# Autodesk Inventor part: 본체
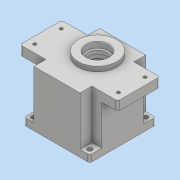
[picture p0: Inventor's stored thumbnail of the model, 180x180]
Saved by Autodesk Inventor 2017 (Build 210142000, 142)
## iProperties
Part Number: 본체
Material: 일반
Document SubType Name: Modeling
Designer: user
Density: 1 g/cm^3
Appearance: 기본값
Author: user
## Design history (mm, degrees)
sketch "스케치3"
  geometry: L1 (33, 47)-(-33, 47); L2 (-33, 47)-(-33, -47); L3 (-33, -47)-(33, -47); L4 (33, -47)-(33, 47); L5 (33, 47)-(-33, -47); L6 (-33, 47)-(33, -47); L7 (70, 30)-(-70, 30); L8 (-70, 30)-(-70, -30); L9 (-70, -30)-(70, -30); L10 (70, -30)-(70, 30); L11 (70, 30)-(-70, -30); L12 (-70, 30)-(70, -30); 1 further point
  constraints: 24 end point, 4 midpoint, 4 parallel, 2 horizontal, 2 perpendicular
  dimensions: "d12" = 66 distance of L3.end L2.end; "d13" = 94 distance of L2.end L1.end; "d14" = 140 distance of L9.end L8.end; "d15" = 60 distance of L8.end L7.end
extrude "돌출2" new body sketch "스케치3" distance "d16" = 13; taper "d17" = 0 deg
node "작업 평면1"
sketch "스케치4"
  geometry: L1 (-47, 47)-(47, 47); L2 (47, 47)-(47, -47); L3 (47, -47)-(-47, -47); L4 (-47, -47)-(-47, 47); L5 (-47, 47)-(47, -47); L6 (47, 47)-(-47, -47); 1 further point
  constraints: 12 end point, 2 midpoint, 2 parallel, 1 horizontal, 1 perpendicular
  dimensions: "d19" = 94 distance of L2.end L3.end; "d20" = 94 distance of L1.end L2.end
extrude "돌출3" join sketch "스케치4" distance "d21" = 10; taper "d22" = 0 deg
sketch "스케치5"
  geometry: L1 (-33, -30)-(-33, -47) reference; L2 (33, 47)-(-33, 47); L3 (-33, 47)-(-33, -47); L4 (-33, -47)-(33, -47); L5 (33, -47)-(33, 47); L6 (33, 47)-(-33, -47); L7 (-33, 47)-(33, -47); L8 (-47, 47)-(-47, -47) reference; L9 (47, 30)-(-47, 30); L10 (-47, 30)-(-47, -30); L11 (-47, -30)-(47, -30); L12 (47, -30)-(47, 30); L13 (47, 30)-(-47, -30); L14 (-47, 30)-(47, -30); L15 (70, 30)-(33, 30) reference; 1 further point
  constraints: 24 end point, 4 midpoint, 4 parallel, 2 horizontal, 2 perpendicular, 2 point on line
extrude "돌출4" join sketch "스케치5" distance "d23" = 70; taper "d24" = 0 deg
sketch "스케치6"
  geometry: C1 r 27.5 at (0, 11); 1 further point
  constraints: 1 centre point, 1 vertical alignment
  dimensions: "d25" = 55 diameter of C1; "d26" = 11 distance of point (0, 0) C1.centre
extrude "돌출5" join sketch "스케치6" distance "d27" = 7; taper "d28" = 0 deg
hole "구멍1" diameter "d31" = 32; stored, may be unused: countersink angle "d35" = 90 deg, drill point angle "d37" = 0 deg; dims "d29" = 10, "d30" = 10, "d32" = 6, "d33" = 4, "d34" = 2, "d36" = 8.3
sketch "스케치7"
  geometry: C1 r 12.5 at (0, 0); C2 r 16 at (0, 0) reference; 1 further point
  constraints: 1 centre point, 1 concentric
  dimensions: "d38" = 25 diameter of C1
extrude "돌출6" cut sketch "스케치7" distance "d39" = 4.7; taper "d40" = 0 deg
sketch "스케치8"
  geometry: C1 r 17.5 at (0, 0); C2 r 16 at (0, 0) reference; 1 further point
  constraints: 1 centre point, 1 concentric
  dimensions: "d41" = 35 diameter of C1
extrude "돌출7" cut sketch "스케치8" distance "d42" = 10; taper "d43" = 0 deg
sketch "스케치9"
  geometry: C1 r 43 at (0, 0); 1 further point
  constraints: 2 coincident, 1 centre point
  dimensions: "d44" = 86 diameter of C1
extrude "돌출8" cut sketch "스케치9" distance "d45" = 9; taper "d46" = 0 deg
sketch "스케치10"
  geometry: C1 r 40 at (0, 0); C2 r 43 at (0, 0) reference; 1 further point
  constraints: 1 centre point, 1 concentric
  dimensions: "d47" = 80 diameter of C1
extrude "돌출9" cut sketch "스케치10" distance "d48" = 62; taper "d49" = 0 deg
sketch "스케치11"
  geometry: 2 further points
  dimensions: "d50" = 19 vertical distance of point (0, 0) point (-60, 19); "d51" = 60 horizontal distance of point (0, 0) point (-60, 19)
hole "구멍2" sketch "스케치11" at (-60, 19) diameter "d52" = 4.5; stored, may be unused: countersink angle "d56" = 90 deg, drill point angle "d58" = 0 deg; dims "d53" = 6, "d54" = 10, "d55" = 5, "d57" = 13
sketch "스케치12"
  geometry: 2 further points
  dimensions: "d65" = 40 horizontal distance of point (0, 0) point (40, 40); "d66" = 40 horizontal distance of point (0, 0) point (40, 40)
hole "구멍3" sketch "스케치12" at (40, 40) diameter "d67" = 7; stored, may be unused: countersink angle "d71" = 90 deg, drill point angle "d73" = 0 deg; dims "d68" = 6, "d69" = 10, "d70" = 5, "d72" = 30
sketch "스케치13"
  geometry: C1 r 21 at (0, 11); C2 r 15 at (0, -20); 1 further point
  constraints: 2 centre point, 2 vertical alignment
  dimensions: "d80" = 42 diameter of C1; "d81" = 30 diameter of C2; "d82" = 11 distance of point (0, 0) C1.centre; "d83" = 20 distance of C2.centre point (0, 0)
extrude "돌출10" join sketch "스케치13" distance "d84" = 7; taper "d85" = 0 deg
hole "구멍4" diameter "d88" = 35; stored, may be unused: countersink angle "d92" = 90 deg, drill point angle "d94" = 0 deg; dims "d86" = 10, "d87" = 10, "d89" = 6, "d90" = 10, "d91" = 5, "d93" = 10
sketch "스케치14"
  geometry: C1 r 11 at (0, -20); A1 r 15 centre (0, -20) between (-8.978, -7.984) and (8.978, -7.984) reference; 1 further point
  constraints: 1 centre point, 1 concentric
  dimensions: "d95" = 22 diameter of C1
extrude "돌출11" cut sketch "스케치14" distance "d96" = 7; taper "d97" = 0 deg
sketch "스케치15"
  geometry: C1 r 9.5 at (0, 0); C2 r 11 at (0, 0) reference; 1 further point
  constraints: 1 centre point, 1 concentric
  dimensions: "d98" = 19 diameter of C1
extrude "돌출12" cut sketch "스케치15" distance "d99" = 3; taper "d100" = 0 deg
fillet "모깎기1" dims "d101" = 3
fillet "모깎기2" dims "d102" = 3
fillet "모깎기3" dims "d103" = 3
sketch "스케치16"
  geometry: A1 r 4 centre (-36, 0) between (-36.19, -3.995) and (-36.19, 3.995); A2 r 40 centre (0, 0) between (-39.279, 7.559) and (-39.279, -7.559) reference; A3 r 3 centre (-36.333, 6.992) between (-39.279, 7.559) and (-36.19, 3.995); A4 r 3 centre (-36.333, -6.992) between (-36.19, -3.995) and (-39.279, -7.559); 1 further point
  constraints: 8 point on circle, 4 tangent, 3 centre point, 1 horizontal alignment
  dimensions: "d104" = 8 diameter of A1; "d105" = 36 distance of A1.centre point (0, 0); "d106" = 3 radius of A4; "d107" = 3 radius of A3
extrude "돌출13" join sketch "스케치16" stored distance "d108" = 3; taper "d109" = 0 deg
sketch "스케치17"
  geometry: A1 r 4 centre (-36, 0) between (-36.19, -3.995) and (-36.19, 3.995) reference; 2 further points
  constraints: 1 coincident
hole "구멍5" sketch "스케치17" at (-36, 0) diameter "d110" = 3.242; stored, may be unused: countersink angle "d114" = 90 deg, drill point angle "d116" = 118 deg; dims "d111" = 7, "d112" = 10, "d113" = 5, "d115" = 9
chamfer "모따기1" distance "d117" = 1; stored, may be unused: second distance "d118" = 2, angle "d119" = 45 deg
chamfer "모따기2" distance "d120" = 0.8; stored, may be unused: second distance "d121" = 2, angle "d122" = 45 deg
chamfer "모따기3" distance "d123" = 0.8; stored, may be unused: second distance "d124" = 2, angle "d125" = 60 deg
chamfer "모따기4" distance "d126" = 1; stored, may be unused: second distance "d127" = 2, angle "d128" = 30 deg
sketch "스케치18"
  geometry: L1 (-11, 80)-(77, 80) reference; L2 (5.5, -7)-(60.5, -7) reference; L3 (16.2, -7)-(49.8, -7) reference; 2 further points
  constraints: 1 vertical alignment, 1 other
  dimensions: "d129" = 40 distance from line of L1 point (33, 40)
feature "엠보싱1" sketch "스케치18" dims "d12" = 66, "d13" = 94, "d130" = 0.5, "d131" = 0
node "솔리드2"
pattern_linear "직사각형 패턴1" dims "d61" = 120, "d64" = 38
pattern_linear "직사각형 패턴2" dims "d76" = 80, "d79" = 80
mirror "미러1"
other parameters: "d18" = -67
